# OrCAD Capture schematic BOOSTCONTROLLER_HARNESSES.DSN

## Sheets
1 Page 3: RS232 Harness: title: BoostController Harnesses: RS232; note: 11021181
2 Page 1: ICD Harness: size A; title: Boost Controller Board - Telemetry
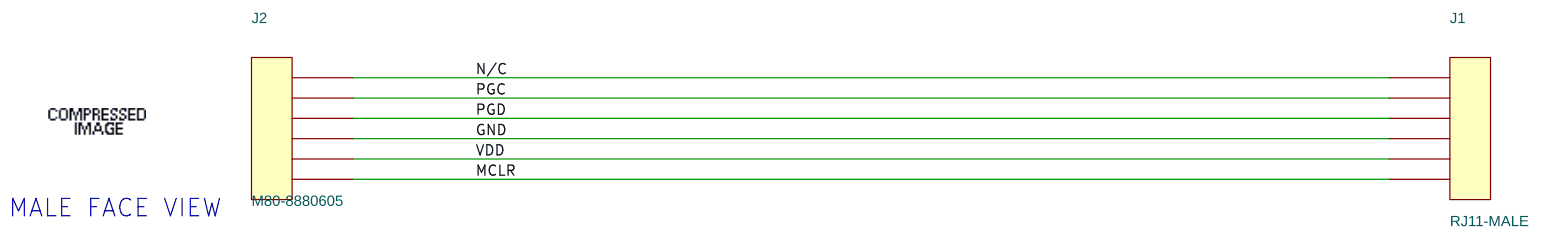
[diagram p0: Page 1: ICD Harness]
3 Page 2: CanBus Harness: title: Boost Controller Board - Telemetry

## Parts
J1  RJ11-MALE
J2  M80-8880605

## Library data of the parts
J1 J2 = CON6

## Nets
GND: J1.4 J2.3
VDD: J1.5 J2.2
MCLR: J1.6 J2.1
N/C: J1.1 J2.6
PGC: J1.2 J2.5
PGD: J1.3 J2.4

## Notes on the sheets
sheet 2
- MALE FACE VIEW
